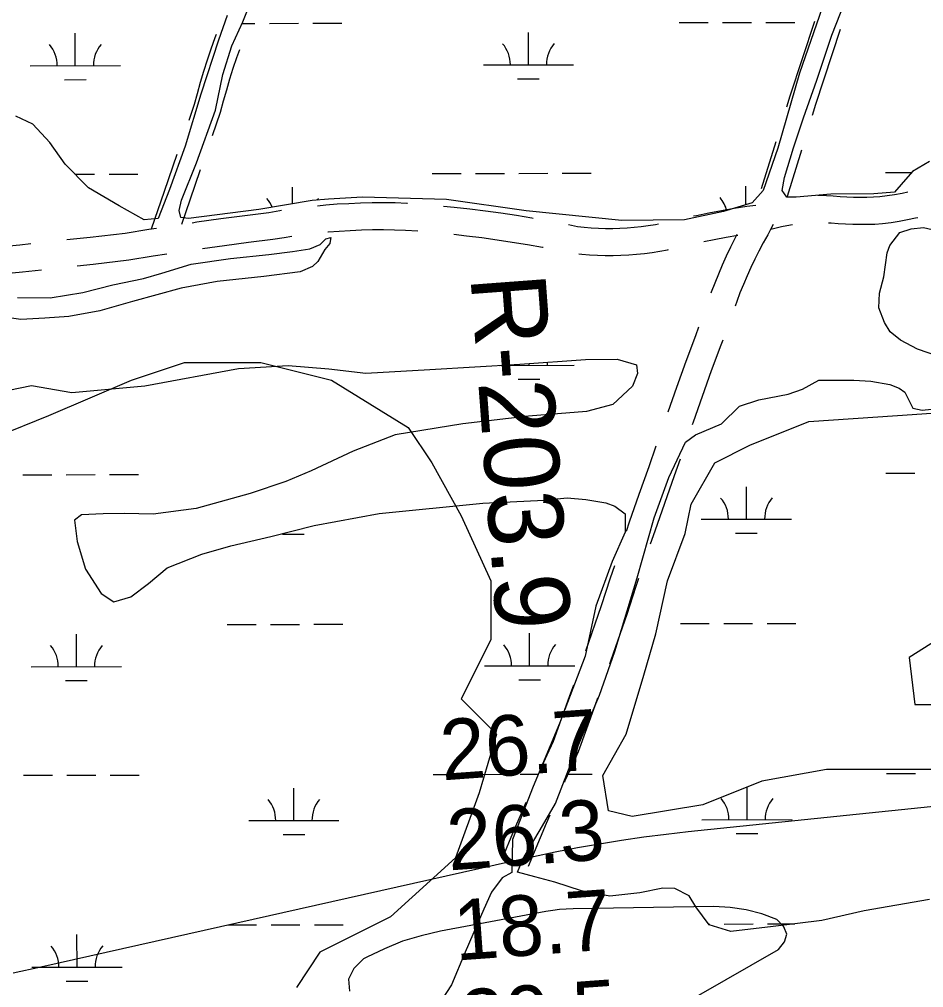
# Model space of a CAD drawing. Extents: x 3329332 to 3367211, y 631066 to 656469.
# Drawn here: x 3333762 to 3334763, y 648850 to 649922 of the extents above; entities that cross this region are included whole.
import ezdxf

# ---------------------------------------------------------------- set-up
doc = ezdxf.new("R2010")
doc.units = 0
for name, color, linetype in [('V-RIVR-RANG', 7, 'Continuous'), ('V-RIVR-RANG-IDEN', 7, 'Continuous'), ('V-ROAD-CNTR', 7, 'Continuous'), ('V-SITE-VEGE', 7, 'Continuous'), ('V-TOPO-MAJR', 7, 'Continuous'), ('V-TOPO-MINR', 7, 'Continuous'), ('V-TOPO-SHOR', 7, 'Continuous'), ('V-WETL-SWMP', 7, 'Continuous')]:
    doc.layers.add(name, color=color, linetype=linetype)

msp = doc.modelspace()

# ---------------------------------------------------------------- linework, layer by layer
at = {"layer": 'V-ROAD-CNTR'}
for p, q in [((3334599.5, 649786.2), (3334583.5, 649734.2)), ((3334628.1, 649777), (3334612.1, 649725.4))]:
    msp.add_line(p, q, dxfattribs=at)
for points in [[(3334642.4, 649919.5), (3334615, 649836.5), (3334611.3, 649824.5)], [(3333979.7, 649905), (3333978.3, 649901.1), (3333974, 649888.8), (3333969.9, 649876.5), (3333965.9, 649864.1), (3333962.2, 649851.7), (3333958.7, 649839.2), (3333955.6, 649827.3), (3333949.5, 649809.8)], [(3334670.9, 649910.3), (3334643.6, 649827.4), (3334639.9, 649815.2)], [(3334005.5, 649888), (3334002.3, 649879.1), (3333998.4, 649867.2), (3333994.6, 649855.3), (3333991.1, 649843.3), (3333987.7, 649831.3), (3333984.3, 649818.5), (3333975.3, 649792.7)], [(3333936.4, 649772), (3333922.2, 649731.2), (3333907.9, 649689.5)], [(3333962.2, 649755), (3333950.6, 649721.5), (3333941.3, 649694.4)], [(3334646.3, 649726.9), (3334648.8, 649726.9), (3334655.9, 649726.7), (3334663, 649726.3), (3334670.8, 649725.6), (3334678.2, 649725.2), (3334685.6, 649724.9), (3334693.1, 649724.8), (3334700.5, 649724.8), (3334707.9, 649725.1), (3334714.9, 649725.5), (3334722.9, 649726.5), (3334731.2, 649727.9), (3334739.5, 649729.4), (3334745.7, 649730.7)], [(3334091.9, 649715.4), (3334101.1, 649716.3), (3334113.9, 649717.3), (3334126.8, 649718), (3334139.6, 649718.6), (3334152.4, 649718.9), (3334165.3, 649718.9), (3334178.1, 649718.8), (3334191.1, 649718.3), (3334191.8, 649718.3)], [(3334231.7, 649715), (3334243.3, 649713.9), (3334260.6, 649711.9), (3334277.9, 649709.8), (3334295.2, 649707.4), (3334312.4, 649704.8), (3334329.5, 649701.9), (3334330.7, 649701.7)], [(3334508.5, 649704), (3334511.6, 649704.7), (3334525.5, 649707.6), (3334539.5, 649710.2), (3334553.5, 649712.5), (3334567.5, 649714.7), (3334577.6, 649716.1)], [(3333953.2, 649696.6), (3333958.4, 649697.4), (3333985, 649701.1), (3334011.7, 649704.6), (3334038, 649707.9), (3334050.2, 649710), (3334052.3, 649710.3)], [(3334657.8, 649696.6), (3334660.8, 649696.4), (3334668.5, 649695.7), (3334676.7, 649695.2), (3334684.8, 649694.9), (3334693, 649694.8), (3334701.1, 649694.8), (3334709.2, 649695.1), (3334717.8, 649695.6), (3334727.2, 649696.9), (3334736.3, 649698.3), (3334745.3, 649700), (3334754.3, 649701.9), (3334757, 649702.5)], [(3333814.5, 649677.8), (3333840.3, 649680.6), (3333879, 649685.1), (3333905.2, 649689.4), (3333913.6, 649690.7)], [(3334370.1, 649694.4), (3334380, 649692.3), (3334387.4, 649691.6), (3334395.2, 649690.9), (3334403.1, 649690.5), (3334411, 649690.3), (3334419, 649690.3), (3334426.9, 649690.5), (3334434.8, 649690.9), (3334442.6, 649691.5), (3334450.5, 649692.4), (3334458.3, 649693.4), (3334466.2, 649694.6), (3334469.5, 649695.2)], [(3334596.8, 649694.7), (3334593.7, 649689.1), (3334590.7, 649683.3), (3334585.6, 649674.2), (3334580.8, 649665.2), (3334576.2, 649656.1), (3334571.9, 649646.9), (3334567.7, 649637.6), (3334563.7, 649628.3), (3334559.9, 649618.8), (3334556.3, 649609.3), (3334554.5, 649604.2)], [(3334593.9, 649689.3), (3334594.1, 649689.3), (3334600, 649691), (3334605.9, 649692.4), (3334611.9, 649693.6), (3334617.9, 649694.7)], [(3333964.6, 649668), (3333989.1, 649671.4), (3334015.5, 649674.9), (3334042.4, 649678.2), (3334055, 649680.3), (3334063.7, 649681.7)], [(3334103.4, 649686.3), (3334103.7, 649686.4), (3334116, 649687.3), (3334128.3, 649688.1), (3334140.6, 649688.6), (3334152.8, 649688.9), (3334165.1, 649688.9), (3334177.4, 649688.8), (3334189.5, 649688.4), (3334203.3, 649687.4)], [(3334243.1, 649683.7), (3334257.1, 649682.1), (3334274, 649680), (3334290.9, 649677.7), (3334307.7, 649675.1), (3334324.5, 649672.4), (3334341.3, 649669.4), (3334342, 649669.3)], [(3334519.8, 649675.8), (3334531.2, 649678.1), (3334544.7, 649680.6), (3334557.7, 649682.8)], [(3334556.6, 649683.6), (3334554.2, 649679), (3334549.3, 649669.3), (3334544.6, 649659.5), (3334540.2, 649649.7), (3334536, 649639.7), (3334531.9, 649629.7), (3334528.1, 649619.6), (3334527.7, 649618.4)], [(3333675.9, 649659.1), (3333685, 649661.2), (3333697.4, 649663.7), (3333709.9, 649666), (3333722.7, 649668.2), (3333762.3, 649672.2), (3333774.7, 649673.5)], [(3333826, 649648.9), (3333843.7, 649650.8), (3333883.2, 649655.4), (3333909.9, 649659.8), (3333925.1, 649662.1)], [(3334381.3, 649662), (3334384.6, 649661.7), (3334393.3, 649661), (3334402, 649660.6), (3334410.6, 649660.3), (3334419.3, 649660.3), (3334428, 649660.5), (3334436.7, 649661), (3334445.4, 649661.7), (3334454, 649662.6), (3334462.6, 649663.7), (3334471.2, 649665), (3334479.7, 649666.6), (3334480.8, 649666.8)], [(3333687.2, 649630.9), (3333691.3, 649631.8), (3333703.2, 649634.3), (3333715.1, 649636.5), (3333726.7, 649638.5), (3333765.4, 649642.3), (3333786.2, 649644.5)], [(3334514.1, 649580.8), (3334510.6, 649571.5), (3334500, 649542.9), (3334489.6, 649514.2), (3334480, 649486.8)], [(3334540.8, 649566.6), (3334538.6, 649560.9), (3334528.1, 649532.6), (3334517.9, 649504.2), (3334507.9, 649475.7), (3334506.8, 649472.6)], [(3334466.9, 649449), (3334458.8, 649426.4), (3334447.9, 649395.7), (3334437.2, 649364.9), (3334433.7, 649354.7)], [(3334493.7, 649434.8), (3334487, 649416.3), (3334476.2, 649385.7), (3334465.5, 649355.1), (3334460.5, 649340.5)], [(3334420.8, 649316.8), (3334416.2, 649303.2), (3334406.1, 649272.4), (3334388.7, 649222.1)], [(3334447.7, 649302.6), (3334444.7, 649293.7), (3334434.5, 649262.8), (3334417, 649212.1), (3334415.5, 649207.9)], [(3334375.4, 649184.4), (3334370.9, 649171.7), (3334352.9, 649122.1), (3334346, 649106.9), (3334338.9, 649091.4)], [(3334402.2, 649170.2), (3334399.1, 649161.6), (3334380.7, 649110.7), (3334373.3, 649094.4), (3334366.1, 649078.8), (3334365.5, 649077.3)], [(3334322.8, 649054.8), (3334317.8, 649043.4), (3334311, 649027.4), (3334304.2, 649011.4), (3334297.6, 648995.4)], [(3334349.3, 649040.7), (3334345.3, 649031.5), (3334338.6, 649015.7), (3334331.9, 648999.8), (3334325.3, 648983.9)]]:
    msp.add_lwpolyline(points, dxfattribs=at)
at = {"layer": 'V-SITE-VEGE'}
for p, q in [((3333885.9, 649522.2), (3333944.6, 649541.8)), ((3333944.6, 649541.8), (3334029.4, 649541.8)), ((3334029.4, 649541.8), (3334107.7, 649522.2)), ((3333794.5, 649483), (3333885.9, 649522.2)), ((3334107.7, 649522.2), (3334192.6, 649469.9)), ((3333729.2, 649456.9), (3333794.5, 649483)), ((3334192.6, 649469.9), (3334218.7, 649430.8)), ((3334218.7, 649430.8), (3334251.3, 649372)), ((3334251.3, 649372), (3334283.9, 649300.2)), ((3334283.9, 649300.2), (3334283.9, 649234.9)), ((3334283.9, 649234.9), (3334251.3, 649169.6)), ((3334251.3, 649169.6), (3334290.4, 649130.4)), ((3334290.4, 649130.4), (3334270.9, 649065.2)), ((3334270.9, 649065.2), (3334244.8, 648993.3)), ((3334244.8, 648993.3), (3334173, 648928)), ((3334173, 648928), (3334094.7, 648888.9)), ((3334094.7, 648888.9), (3334068.6, 648849.7))]:
    msp.add_line(p, q, dxfattribs=at)
for points in [[(3334825.5, 649091.3), (3334740.7, 649091.3), (3334655.9, 649091.3), (3334584.1, 649078.2), (3334518.8, 649052.1), (3334440.5, 649039), (3334414.4, 649045.6), (3334407.9, 649084.7), (3334434, 649130.4), (3334453.6, 649195.7), (3334466.6, 649241.4), (3334479.7, 649300.2), (3334499.2, 649352.4), (3334505.8, 649385.1), (3334531.9, 649430.8), (3334571, 649450.3), (3334636.3, 649476.5), (3334734.2, 649483), (3334825.5, 649489.5)], [(3334799.4, 649248), (3334747.2, 649215.3), (3334753.7, 649163.1), (3334805.9, 649163.1)]]:
    msp.add_lwpolyline(points, dxfattribs=at)
at = {"layer": 'V-TOPO-MAJR'}
msp.add_lwpolyline([(3335210.7, 649158.3), (3335124.9, 649090.3), (3335124.7, 649090.1), (3335120.8, 649087.4), (3335117.8, 649085.9), (3335114.6, 649085.2), (3334502.6, 649022.2), (3334478, 649019.4), (3334453.3, 649016.3), (3334428.7, 649012.7), (3334404.2, 649008.7), (3334379.8, 649004.3), (3334355.4, 648999.6), (3334331.1, 648994.6), (3334306.8, 648989.3), (3333785.8, 648872.5), (3333755, 648865.6)], dxfattribs=at)
at = {"layer": 'V-TOPO-MINR'}
msp.add_lwpolyline([(3334514.2, 648841.2), (3334602.5, 648891.9), (3334609.2, 648900.5), (3334611.8, 648909), (3334608.4, 648917.1), (3334600.9, 648925), (3334584, 648931.3), (3334566.8, 648936), (3334549.1, 648938.4), (3334531.1, 648939.4), (3334375.2, 648937), (3334367.6, 648936.7), (3334360.1, 648936.1), (3334352.5, 648935.1), (3334345, 648933.9), (3334228.2, 648912.2), (3334207, 648907.2), (3334186.3, 648901), (3334166.2, 648892.8), (3334146.5, 648883.4), (3334142.8, 648881.4), (3334132.2, 648870.7), (3334126.2, 648859), (3334127.3, 648845.9)], dxfattribs=at)
at = {"layer": 'V-TOPO-SHOR'}
msp.add_lwpolyline([(3333759.8, 649613.6), (3333796, 649613.5), (3333832.1, 649619.3), (3333865.5, 649627.8), (3333899.3, 649634.8), (3333919.6, 649640.6), (3333952.2, 649650.6), (3333995.7, 649656.8), (3334038.1, 649661.4), (3334064.5, 649664.5), (3334083.6, 649667.6), (3334094.8, 649672.6), (3334101.1, 649678.8), (3334106.9, 649680), (3334106.5, 649678.4), (3334105.7, 649673.4), (3334100.3, 649666.8), (3334092.5, 649653.6), (3334086.6, 649648.2), (3334073, 649642.3), (3334032.6, 649637), (3333980.9, 649631.6), (3333940.9, 649624.2), (3333887.3, 649609.5), (3333851.1, 649599.1), (3333816.5, 649592.9), (3333790.1, 649591), (3333763.3, 649589.5), (3333737.3, 649593)], dxfattribs=at)
at = {"layer": 'V-WETL-SWMP'}
for p, q in [((3333991.8, 649925.8), (3333982.4, 649898.6)), ((3334008.5, 649917.2), (3334022.8, 649917.2)), ((3334038.8, 649917.2), (3334070.8, 649917.3)), ((3334086.8, 649917.3), (3334118.8, 649917.4)), ((3334492.7, 649918.1), (3334524.7, 649918.1)), ((3334540.7, 649918.2), (3334572.7, 649918.2)), ((3334588.7, 649918.3), (3334620.7, 649918.3)), ((3333823.8, 649870.4), (3333823.7, 649906.4)), ((3334325.7, 649871.3), (3334325.6, 649907.3)), ((3333982.4, 649898.6), (3333963, 649839)), ((3333773.8, 649870.3), (3333873.8, 649870.5)), ((3334275.7, 649871.2), (3334375.7, 649871.4)), ((3333811.8, 649854.9), (3333835.8, 649855)), ((3334313.7, 649855.9), (3334337.7, 649855.9)), ((3333963, 649839), (3333945.6, 649781.4)), ((3333776.7, 649805.7), (3333757.9, 649814.6)), ((3333795.5, 649785.3), (3333776.7, 649805.7)), ((3333812.7, 649761.2), (3333795.5, 649785.3)), ((3333945.6, 649781.4), (3333928.3, 649733.3)), ((3333838.4, 649735), (3333812.7, 649761.2)), ((3333823.4, 649750.3), (3333845.2, 649750.3)), ((3333861.2, 649750.4), (3333893.2, 649750.4)), ((3334219.1, 649751.1), (3334251.1, 649751.1)), ((3334267.1, 649751.1), (3334299.1, 649751.2)), ((3334315.1, 649751.2), (3334347.1, 649751.3)), ((3334363.1, 649751.3), (3334395.1, 649751.4)), ((3334721, 649752), (3334749.7, 649752.1)), ((3333872.3, 649715.1), (3333838.4, 649735)), ((3333928.3, 649733.3), (3333915.7, 649701.4)), ((3334064.5, 649717.5), (3334064.5, 649736)), ((3334566.4, 649716.5), (3334566.4, 649737)), ((3333900, 649699.9), (3333872.3, 649715.1)), ((3333915.7, 649701.4), (3333900, 649699.9)), ((3334216.3, 649534.2), (3334316.2, 649539.9)), ((3334316.2, 649539.9), (3334388.9, 649545)), ((3334326.3, 649538.6), (3334326.3, 649540.6)), ((3334388.9, 649545), (3334424, 649545.5)), ((3334424, 649545.5), (3334445.4, 649539.2)), ((3333900.9, 649515.8), (3334004.5, 649535)), ((3334004.5, 649535), (3334059.4, 649538.6)), ((3334059.4, 649538.6), (3334104.4, 649534.9)), ((3334104.4, 649534.9), (3334145.7, 649530.1)), ((3334145.7, 649530.1), (3334216.3, 649534.2)), ((3334293.4, 649538.6), (3334376.3, 649538.7)), ((3334446.5, 649529.8), (3334440.7, 649515.7)), ((3334445.4, 649539.2), (3334446.5, 649529.8)), ((3334314.3, 649523.2), (3334338.3, 649523.2)), ((3333715.2, 649504), (3333775.3, 649516.4)), ((3333775.3, 649516.4), (3333819.8, 649508.5)), ((3333819.8, 649508.5), (3333900.9, 649515.8)), ((3334440.7, 649515.7), (3334419.2, 649495.3)), ((3334389.9, 649487.5), (3334325.6, 649482.3)), ((3334419.2, 649495.3), (3334389.9, 649487.5)), ((3334325.6, 649482.3), (3334252.9, 649474)), ((3334252.9, 649474), (3334178, 649461.6)), ((3334178, 649461.6), (3334131.5, 649443.8)), ((3334131.5, 649443.8), (3334084.9, 649421.9)), ((3334084.9, 649421.9), (3334057.1, 649409.9)), ((3333765.8, 649417.5), (3333797.8, 649417.6)), ((3333813.8, 649417.6), (3333845.8, 649417.7)), ((3333861.8, 649417.7), (3333893.8, 649417.8)), ((3334721.6, 649419.3), (3334753.6, 649419.4)), ((3334057.1, 649409.9), (3334017.4, 649396.9)), ((3334567.1, 649368.3), (3334567, 649404.3)), ((3334017.4, 649396.9), (3333957.7, 649380.2)), ((3334275.2, 649386.1), (3334343.2, 649389.2)), ((3334343.2, 649389.2), (3334368.4, 649391.8)), ((3334368.4, 649391.8), (3334389.3, 649390.2)), ((3334389.3, 649390.2), (3334411.2, 649386.5)), ((3333957.7, 649380.2), (3333910.1, 649374)), ((3334160.2, 649374.8), (3334275.2, 649386.1)), ((3334411.2, 649386.5), (3334421.2, 649382.8)), ((3334421.2, 649382.8), (3334432.7, 649374.4)), ((3333830.6, 649373.1), (3333822.8, 649367.3)), ((3333854.7, 649374.1), (3333830.6, 649373.1)), ((3333878.2, 649374.6), (3333854.7, 649374.1)), ((3333910.1, 649374), (3333878.2, 649374.6)), ((3334088.5, 649361.2), (3334160.2, 649374.8)), ((3334432.7, 649374.4), (3334432.7, 649354)), ((3334517.1, 649368.2), (3334617.1, 649368.4)), ((3333822.8, 649367.3), (3333825.9, 649343.8)), ((3334040.3, 649349.3), (3334088.5, 649361.2)), ((3333995.9, 649338.9), (3334040.3, 649349.3)), ((3334053.2, 649351.9), (3334077.2, 649351.9)), ((3334432.7, 649354), (3334418.5, 649321.6)), ((3334555.1, 649352.8), (3334579.1, 649352.9)), ((3333825.9, 649343.8), (3333835.2, 649312.9)), ((3333963.9, 649329.5), (3333995.9, 649338.9)), ((3333925.7, 649314.4), (3333963.9, 649329.5)), ((3333904.8, 649297.1), (3333925.7, 649314.4)), ((3334418.5, 649321.6), (3334400.1, 649272)), ((3333835.2, 649312.9), (3333852.5, 649286.2)), ((3333885.4, 649282.5), (3333904.8, 649297.1)), ((3333852.5, 649286.2), (3333866.6, 649276.8)), ((3333866.6, 649276.8), (3333885.4, 649282.5)), ((3334400.1, 649272), (3334388.6, 649216.5)), ((3333992, 649251.8), (3334024, 649251.8)), ((3334040, 649251.9), (3334072, 649251.9)), ((3334088, 649252), (3334120, 649252)), ((3334493.9, 649252.7), (3334525.9, 649252.8)), ((3334541.9, 649252.8), (3334573.9, 649252.9)), ((3334589.9, 649252.9), (3334621.9, 649253)), ((3333825, 649205), (3333825, 649241)), ((3334326.9, 649206), (3334326.9, 649242)), ((3334388.6, 649216.5), (3334360.2, 649142.3)), ((3333775, 649204.9), (3333875, 649205.1)), ((3334276.9, 649205.9), (3334376.9, 649206.1)), ((3333813.1, 649189.6), (3333837.1, 649189.6)), ((3334315, 649190.5), (3334339, 649190.6)), ((3334360.2, 649142.3), (3334330.9, 649072.2)), ((3333766.4, 649084.8), (3333798.4, 649084.9)), ((3333814.4, 649084.9), (3333846.4, 649085)), ((3333862.4, 649085), (3333894.4, 649085.1)), ((3334220.3, 649085.7), (3334252.3, 649085.8)), ((3334268.3, 649085.8), (3334300.3, 649085.9)), ((3334316.3, 649085.9), (3334336.6, 649085.9)), ((3334368.1, 649086), (3334396.3, 649086)), ((3334722.2, 649086.7), (3334754.2, 649086.7)), ((3334065.8, 649034.7), (3334065.8, 649070.7)), ((3334330.9, 649072.2), (3334307.8, 649013.7)), ((3334567.7, 649035.6), (3334567.7, 649071.6)), ((3334517.7, 649035.5), (3334617.7, 649035.7)), ((3334015.8, 649034.6), (3334115.8, 649034.8)), ((3334053.9, 649019.2), (3334077.9, 649019.3)), ((3334555.8, 649020.2), (3334579.8, 649020.2)), ((3334307.8, 649013.7), (3334307.3, 648977.3)), ((3334296.5, 648971.1), (3334284.8, 648955.3)), ((3334307.3, 648977.3), (3334296.5, 648971.1)), ((3334284.8, 648955.3), (3334276.3, 648936.7)), ((3334276.3, 648936.7), (3334255.4, 648888.8)), ((3333992.6, 648919.1), (3334024.6, 648919.2)), ((3334040.6, 648919.2), (3334072.6, 648919.2)), ((3334088.6, 648919.3), (3334120.6, 648919.3)), ((3334525.3, 648920.1), (3334526.5, 648920.1)), ((3334542.5, 648920.1), (3334574.5, 648920.2)), ((3334590.5, 648920.2), (3334620.7, 648920.3)), ((3333825.7, 648872.4), (3333825.6, 648908.4)), ((3334255.4, 648888.8), (3334240.6, 648852.8)), ((3333775.7, 648872.3), (3333875.7, 648872.4)), ((3333813.7, 648856.9), (3333837.7, 648856.9)), ((3334240.6, 648852.8), (3334218.9, 648820.3))]:
    msp.add_line(p, q, dxfattribs=at)
for points in [[(3334657.1, 649952.8), (3334625.9, 649862), (3334601.7, 649779.2), (3334585.7, 649732.2), (3334573.3, 649718.6), (3334541.8, 649709), (3334498.6, 649699.7), (3334429.1, 649699), (3334323, 649709.6), (3334234.8, 649722.1), (3334142, 649725), (3334104.3, 649722.7), (3334086, 649721.2), (3334026.9, 649711.1), (3333949.2, 649701.1), (3333940.7, 649702.3), (3333938.7, 649710.1), (3333941.5, 649721.7), (3333958.2, 649762.9), (3333978.9, 649821.1), (3333987.1, 649860.8), (3333997.2, 649892.2), (3334009.3, 649919), (3334028.8, 649968)], [(3334769.9, 649764.2), (3334750.8, 649753.4), (3334738.4, 649739), (3334731, 649730.5), (3334708, 649728.6), (3334660.6, 649728.2), (3334622.2, 649724.8), (3334611.7, 649724.8), (3334606.6, 649732.2), (3334609.4, 649746.6), (3334619.1, 649779.6), (3334630.4, 649812.6), (3334645.2, 649854.5), (3334661.6, 649904.3), (3334676, 649940.8)], [(3334781.3, 649548.1), (3334756.4, 649556.7), (3334737.8, 649566.4), (3334726.1, 649575.8), (3334719.9, 649585.9), (3334713.7, 649602.2), (3334714.5, 649618.5), (3334719.2, 649636.8), (3334723.1, 649663.2), (3334725.8, 649671.4), (3334737.1, 649685.7), (3334749.6, 649689.6), (3334763.2, 649691.1), (3334787.3, 649685.7)], [(3334474.4, 648959.7), (3334448.9, 648954.7), (3334415.6, 648950.9), (3334384.3, 648956.7), (3334354.9, 648966.4), (3334332.8, 648972.2), (3334313.5, 648977.7), (3334319.3, 648992.1), (3334341.1, 649028.9), (3334355.6, 649053.4), (3334376.2, 649107), (3334404.3, 649173.4), (3334421.4, 649222), (3334446, 649303.5), (3334464.7, 649370), (3334481.1, 649414.6), (3334499.4, 649453.5), (3334510.7, 649461.6), (3334539.4, 649474), (3334559.3, 649493.4), (3334580.7, 649500.4), (3334613.3, 649506.6), (3334629.2, 649512.4), (3334647.1, 649522.1), (3334686, 649522.4), (3334705, 649521.2), (3334726, 649517.3), (3334736.1, 649513.4), (3334742.3, 649509.1), (3334751.2, 649491.2), (3334761.7, 649488.9), (3334802.9, 649493.5)], [(3334769.7, 648947.4), (3334697.3, 648934.7), (3334650.5, 648923.9), (3334596.7, 648917.4), (3334549.8, 648912), (3334525.9, 648919.4), (3334511.2, 648939.2), (3334503.5, 648951.5), (3334487.6, 648959.3), (3334474.4, 648959.7)]]:
    msp.add_lwpolyline(points, dxfattribs=at)
for centre, start, end in [((3333768.5, 649870.7), 359.3365, 40.8801), ((3333879, 649871), 139.3365, 180.8801), ((3334270.4, 649871.7), 359.3365, 40.8801), ((3334380.9, 649871.9), 139.3365, 180.8801), ((3334009.3, 649700.4), 22.1341, 40.8801), ((3334119.8, 649700.6), 139.3365, 143.4002), ((3334511.2, 649701.3), 14.3386, 40.8801), ((3334271.1, 649539), 359.3365, 0.4791), ((3334381.6, 649539.2), 175.4722, 180.8801), ((3334511.9, 649368.7), 359.3365, 40.8801), ((3334622.4, 649368.9), 139.3365, 180.8801), ((3333769.8, 649205.4), 359.3365, 40.8801), ((3333880.3, 649205.6), 139.3365, 180.8801), ((3334271.7, 649206.3), 359.3365, 40.8801), ((3334382.2, 649206.6), 139.3365, 180.8801), ((3334010.6, 649035), 359.3365, 40.8801), ((3334121.1, 649035.2), 139.3365, 180.8801), ((3334512.5, 649036), 359.3365, 40.8801), ((3334623, 649036.2), 139.3365, 180.8801), ((3333770.4, 648872.7), 359.3365, 40.8801), ((3333880.9, 648872.9), 139.3365, 180.8801)]:
    msp.add_arc(centre, 35.2, start, end, dxfattribs=at)

# ---------------------------------------------------------------- texts
at = {"layer": 'V-RIVR-RANG'}
for s, p in [('26.7', (3334230.3, 649079.1)), ('26.3', (3334237.7, 648979.4)), ('18.7', (3334245.1, 648879.6)), ('20.5', (3334252.6, 648779.9))]:
    msp.add_text(s, height=67, rotation=4.1183, dxfattribs=at).set_placement(p)
at = {"layer": 'V-RIVR-RANG-IDEN'}
msp.add_text('R-203.9', height=83, rotation=274.2621, dxfattribs=at).set_placement((3334261.3, 649637))

doc.saveas('drawing.dxf')
